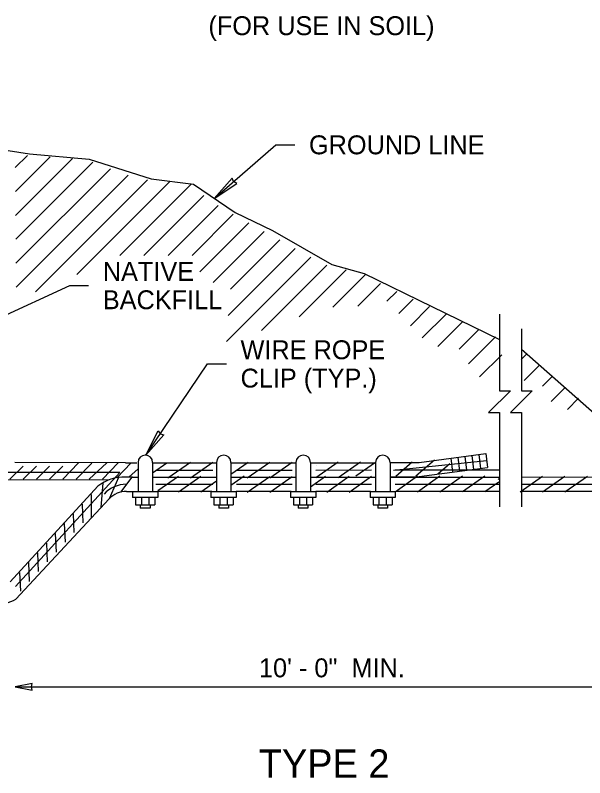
# Model space of a CAD drawing. Extents: x 99861 to 103151, y 100000 to 102076.
# Drawn here: x 100219 to 100701, y 100780 to 101426 of the extents above; entities that cross this region are included whole.
import ezdxf

# ---------------------------------------------------------------- set-up
doc = ezdxf.new("R2010")
doc.units = 0
for name, color, linetype in [('Level 1', 7, 'Continuous'), ('Level 10', 7, 'Continuous'), ('Level 15', 7, 'Continuous'), ('Level 18', 7, 'Continuous'), ('Level 20', 7, 'Continuous'), ('Level 28', 7, 'Continuous'), ('Level 3', 7, 'Continuous'), ('Level 4', 7, 'Continuous')]:
    doc.layers.add(name, color=color, linetype=linetype)

msp = doc.modelspace()

# ---------------------------------------------------------------- linework, layer by layer
at = {"layer": 'Level 1'}
for p, q in [((100616.94, 101054.52), (100618.49, 101042.62)), ((100312, 101046.45), (100218.25, 101047)), ((100312, 101046.45), (100321.65, 101046.45)), ((100473.91, 101043.94), (100473.91, 101043.94)), ((100317.76, 101034.45), (100312, 101034.45)), ((100317.76, 101034.45), (100322.9, 101034.45)), ((100297.67, 101032.04), (100153.96, 101032.42)), ((100312.8, 101022.45), (100317.94, 101022.45)), ((100219.24, 100931.28), (100298.16, 101016.07))]:
    msp.add_line(p, q, dxfattribs=at)
for points in [[(100628.45, 101172.45), (100628.45, 101107.66), (100637.74, 101107.66), (100619.16, 101089.08), (100628.45, 101089.08), (100628.45, 101029.73)], [(100647.03, 101159.99), (100647.03, 101107.66), (100656.32, 101107.66), (100637.74, 101089.08), (100647.03, 101089.08), (100647.03, 101009.35)], [(100535.91, 101046.94), (100560.43, 101046.86), (100616.94, 101054.52)], [(100335.57, 101046.46), (100388.82, 101046.48)], [(100401.24, 101046.48), (100455.96, 101046.5)], [(100468.57, 101046.51), (100523.17, 101046.53)], [(100535.91, 101034.78), (100560.45, 101035.03), (100618.49, 101042.62)], [(100334.89, 101034.45), (100388.92, 101034.48)], [(100401.23, 101034.48), (100456.26, 101034.5)], [(100468.57, 101034.51), (100523.6, 101034.53)], [(100535.91, 101034.53), (100628.45, 101034.56)], [(100647.37, 101034.57), (100762.09, 101034.61)], [(100288.57, 101026.8), (100214.43, 100945.81)], [(100628.45, 101029.63), (100628.45, 101009.35)], [(100339.33, 101022.46), (100385.06, 101022.47)], [(100405.62, 101022.48), (100452.16, 101022.5)], [(100472.96, 101022.51), (100519.36, 101022.53)], [(100540.96, 101022.53), (100628.45, 101022.56)], [(100647.37, 101022.57), (100772.65, 101022.61)]]:
    msp.add_lwpolyline(points, dxfattribs=at)
for centre, radius, start, end in [((100310.56, 100999.15), 35.32, 87.66549, 128.4992), ((100312.8, 101002.45), 20, 90, 137.05427), ((100200.93, 100963.29), 36.88, 270, 299.75989)]:
    msp.add_arc(centre, radius, start, end, dxfattribs=at)
at = {"layer": 'Level 10'}
for p, q in [((100218.67, 101296.56), (100228.94, 101306.83)), ((100218.67, 101296.56), (100228.94, 101306.83)), ((100218.82, 101276.34), (100248.08, 101305.61)), ((100218.97, 101256.13), (100267.22, 101304.38)), ((100219.12, 101235.91), (100284.3, 101301.09)), ((100219.12, 101235.91), (100284.3, 101301.09)), ((100219.27, 101215.7), (100299.23, 101295.66)), ((100219.42, 101195.48), (100314.17, 101290.23)), ((100235.65, 101191.35), (100330.45, 101286.15)), ((100235.65, 101191.35), (100330.45, 101286.15)), ((100270.73, 101206.06), (100349.12, 101284.45)), ((100307.24, 101222.21), (100367.79, 101282.76)), ((100327.6, 101222.21), (100378.25, 101272.86)), ((100327.6, 101222.21), (100378.25, 101272.86)), ((100347.97, 101222.21), (100390.33, 101264.57)), ((100368.33, 101222.21), (100403.21, 101257.09)), ((100374.92, 101208.43), (100416.33, 101249.84)), ((100374.92, 101208.43), (100416.33, 101249.84)), ((100386.11, 101199.26), (100429.44, 101242.59)), ((100400.96, 101193.74), (100442.56, 101235.34)), ((100398.81, 101171.23), (100455.67, 101228.09)), ((100398.81, 101171.23), (100455.67, 101228.09)), ((100397.39, 101149.44), (100468.79, 101220.84)), ((100427.04, 101158.73), (100482.32, 101214.01)), ((100459.02, 101170.35), (100498.61, 101209.94)), ((100487.48, 101178.44), (100514.73, 101205.68)), ((100508.56, 101179.15), (100527.74, 101198.33)), ((100533.19, 101183.42), (100541.53, 101191.76)), ((100533.19, 101183.42), (100541.53, 101191.76)), ((100543.19, 101173.06), (100555.39, 101185.25)), ((100553.2, 101162.7), (100569.4, 101178.9)), ((100563.2, 101152.34), (100583.41, 101172.54)), ((100563.2, 101152.34), (100583.41, 101172.54)), ((100576.2, 101144.97), (100597.42, 101166.19)), ((100594.4, 101142.81), (100611.43, 101159.84)), ((100602.37, 101130.41), (100625.2, 101153.25)), ((100602.37, 101130.41), (100625.2, 101153.25)), ((100611.75, 101119.43), (100630.41, 101138.09)), ((100646.77, 101134.08), (100651.91, 101139.22)), ((100649.42, 101116.37), (100662.35, 101129.3)), ((100649.42, 101116.37), (100662.35, 101129.3)), ((100664.89, 101111.47), (100672.79, 101119.38)), ((100672.34, 101098.56), (100683.84, 101110.06)), ((100686.03, 101091.88), (100695.41, 101101.27)), ((100686.03, 101091.88), (100695.41, 101101.27))]:
    msp.add_line(p, q, dxfattribs=at)
at = {"layer": 'Level 15'}
for p, q in [((100387.07, 101270.55), (100439.26, 101315.86)), ((100439.27, 101315.86), (100455.27, 101315.86)), ((100194.8, 101164.45), (100264.76, 101196.68)), ((100264.76, 101196.68), (100280.76, 101196.68)), ((100329.23, 101053.11), (100381.35, 101130.33)), ((100381.35, 101130.33), (100397.35, 101130.33)), ((100218.62, 100856.99), (100747.95, 100856.99))]:
    msp.add_line(p, q, dxfattribs=at)
for points in [[(100387.07, 101270.55), (100406.27, 101283.26), (100403.51, 101284.82), (100402.36, 101287.77)], [(100329.23, 101053.11), (100339.53, 101073.7), (100341.41, 101071.16), (100344.48, 101070.37)], [(100218.62, 100856.99), (100232.96, 100854.18), (100232.28, 100856.99), (100232.96, 100859.8)]]:
    msp.add_lwpolyline(points, close=True, dxfattribs=at)
at = {"layer": 'Level 28'}
for p, q in [((100322.59, 101046.98), (100322.58, 101022.67)), ((100334.9, 101046.97), (100334.89, 101022.67)), ((100388.93, 101046.97), (100388.91, 101022.66)), ((100401.24, 101046.96), (100401.22, 101022.65)), ((100456.27, 101046.96), (100456.25, 101022.65)), ((100468.57, 101046.95), (100468.56, 101022.64)), ((100523.6, 101046.94), (100523.59, 101022.64)), ((100535.91, 101046.94), (100535.9, 101022.63)), ((100317.94, 101022.45), (100339.28, 101022.41)), ((100384.28, 101022.44), (100405.62, 101022.39)), ((100451.62, 101022.42), (100472.96, 101022.38)), ((100518.96, 101022.41), (100540.3, 101022.37)), ((100339.28, 101017.31), (100317.94, 101017.32)), ((100325.51, 101017.21), (100325.51, 101010.97)), ((100331.59, 101017.31), (100331.58, 101010.96)), ((100336.71, 101017.31), (100336.71, 101010.96)), ((100405.62, 101017.3), (100384.28, 101017.31)), ((100391.85, 101017.19), (100391.85, 101010.96)), ((100397.92, 101017.3), (100397.92, 101010.95)), ((100403.05, 101017.3), (100403.05, 101010.95)), ((100472.95, 101017.29), (100451.62, 101017.3)), ((100459.19, 101017.18), (100459.18, 101010.94)), ((100465.26, 101017.29), (100465.26, 101010.94)), ((100470.39, 101017.29), (100470.39, 101010.94)), ((100540.29, 101017.27), (100518.95, 101017.29)), ((100526.53, 101017.17), (100526.52, 101010.93)), ((100532.6, 101017.28), (100532.6, 101010.93)), ((100537.73, 101017.27), (100537.72, 101010.92)), ((100324.5, 101010.97), (100324.5, 101008.16)), ((100332.71, 101008.16), (100324.5, 101008.16)), ((100331.41, 101008.16), (100326.34, 101008.16)), ((100332.71, 101010.96), (100332.71, 101008.16)), ((100390.84, 101010.96), (100390.84, 101008.15)), ((100399.05, 101008.15), (100390.84, 101008.15)), ((100397.75, 101008.15), (100392.68, 101008.15)), ((100399.05, 101010.95), (100399.05, 101008.15)), ((100458.18, 101010.94), (100458.18, 101008.14)), ((100466.38, 101008.13), (100458.18, 101008.14)), ((100465.08, 101008.13), (100460.02, 101008.14)), ((100466.38, 101010.94), (100466.38, 101008.13)), ((100525.52, 101010.93), (100525.51, 101008.13)), ((100533.72, 101008.12), (100525.51, 101008.13)), ((100532.42, 101008.12), (100527.36, 101008.13)), ((100533.72, 101010.93), (100533.72, 101008.12))]:
    msp.add_line(p, q, dxfattribs=at)
for points in [[(100317.94, 101022.45), (100317.94, 101017.32)], [(100339.28, 101022.41), (100339.28, 101017.31)], [(100384.28, 101022.44), (100384.28, 101017.31)], [(100405.62, 101022.39), (100405.62, 101017.3)], [(100451.62, 101022.42), (100451.62, 101017.3)], [(100472.96, 101022.38), (100472.95, 101017.29)], [(100518.96, 101022.41), (100518.95, 101017.29)], [(100540.3, 101022.37), (100540.29, 101017.27)], [(100320.51, 101017.32), (100320.5, 101010.97), (100336.71, 101010.96)], [(100386.84, 101017.31), (100386.84, 101010.96), (100403.05, 101010.95)], [(100454.18, 101017.3), (100454.18, 101010.95), (100470.39, 101010.94)], [(100521.52, 101017.28), (100521.52, 101010.93), (100537.72, 101010.92)]]:
    msp.add_lwpolyline(points, dxfattribs=at)
for centre in [(100328.74, 101046.98), (100395.08, 101046.97), (100462.42, 101046.95), (100529.76, 101046.94)]:
    msp.add_arc(centre, 6.15, 359.96715, 179.96715, dxfattribs=at)
at = {"layer": 'Level 3'}
for p, q in [((100181.21, 101316.19), (100230.65, 101308.17)), ((100230.65, 101308.17), (100281.27, 101303.59)), ((100281.27, 101303.59), (100333.64, 101286.99)), ((100333.64, 101286.99), (100369.39, 101282.61)), ((100369.39, 101282.61), (100404.75, 101258.49)), ((100404.75, 101258.49), (100436.44, 101243.42)), ((100647.03, 101142.97), (100753.72, 101048.58))]:
    msp.add_line(p, q, dxfattribs=at)
msp.add_lwpolyline([(100436.44, 101243.42), (100486.67, 101214.59), (100513.95, 101206.9), (100628.45, 101150.94)], dxfattribs=at)
at = {"layer": 'Level 4'}
for p, q in [((100605.06, 101052.83), (100606.59, 101041.07)), ((100610.99, 101053.74), (100612.54, 101041.85)), ((100258.9, 101032.69), (100272.14, 101046.68)), ((100270.1, 101032.69), (100283.6, 101046.2)), ((100281.3, 101032.69), (100296.1, 101046.54)), ((100292.5, 101032.69), (100305.7, 101046.48)), ((100304.61, 101033.97), (100316.82, 101046.45)), ((100334.89, 101038), (100346.95, 101046.46)), ((100347.9, 101033.81), (100366.89, 101047.12)), ((100366.9, 101033.82), (100385.89, 101047.13)), ((100401.23, 101036.9), (100415.85, 101047.14)), ((100415.01, 101033.83), (100434, 101047.14)), ((100434.01, 101033.84), (100453, 101047.15)), ((100491.94, 101047.17), (100472.94, 101033.86)), ((100491.94, 101047.17), (100472.94, 101033.86)), ((100510.93, 101047.17), (100491.94, 101033.86)), ((100510.93, 101047.17), (100491.94, 101033.86)), ((100523.6, 101046.94), (100507.06, 101035.35)), ((100554.75, 101047.13), (100540.78, 101035.04)), ((100573.52, 101048.96), (100557.78, 101035.34)), ((100586.42, 101045.72), (100576.36, 101037.01)), ((100587.21, 101050.49), (100588.75, 101038.73)), ((100593.16, 101051.27), (100594.7, 101039.51)), ((100599.11, 101052.05), (100600.65, 101040.29)), ((100214.1, 101032.69), (100225.3, 101043.89)), ((100225.3, 101032.69), (100236.5, 101043.89)), ((100236.5, 101032.69), (100247.7, 101043.89)), ((100247.7, 101032.69), (100258.9, 101043.89)), ((100314.88, 101034.45), (100322.59, 101041.42)), ((100306.05, 101034.19), (100298.16, 101016.07)), ((100317.38, 101034.45), (100307.85, 101021.78)), ((100356.77, 101035.11), (100339.33, 101022.89)), ((100375.77, 101035.12), (100356.78, 101021.81)), ((100401.23, 101027.64), (100412.39, 101035.46)), ((100415.01, 101021.83), (100434.01, 101035.14)), ((100415.01, 101021.83), (100434.01, 101035.14)), ((100434.01, 101021.84), (100453.01, 101035.15)), ((100434.01, 101021.84), (100453.01, 101035.15)), ((100468.56, 101026.19), (100481.38, 101035.17)), ((100482.25, 101021.86), (100501.24, 101035.17)), ((100482.25, 101021.86), (100501.24, 101035.17)), ((100501.25, 101021.87), (100520.24, 101035.18)), ((100501.25, 101021.87), (100520.24, 101035.18)), ((100559.14, 101035.19), (100540.14, 101021.88)), ((100578.14, 101035.2), (100559.14, 101021.89)), ((100597.14, 101035.2), (100578.14, 101021.89)), ((100616.14, 101035.21), (100597.14, 101021.9)), ((100628.23, 101033.41), (100627.39, 101032.56)), ((100645.98, 101021.91), (100664.97, 101035.22)), ((100664.98, 101021.92), (100683.97, 101035.23)), ((100683.98, 101021.93), (100702.97, 101035.24)), ((100292.67, 101029.61), (100291.03, 101008.79)), ((100388.92, 101031.03), (100375.78, 101021.82)), ((100628.03, 101030.23), (100616.14, 101021.9)), ((100282.79, 101019.89), (100283, 100999.79)), ((100275.22, 101011.63), (100275.92, 100995.81)), ((100267.66, 101003.37), (100268.36, 100987.55)), ((100260.1, 100995.11), (100260.8, 100979.28)), ((100252.54, 100986.85), (100253.23, 100971.02)), ((100244.97, 100978.59), (100245.67, 100962.76)), ((100237.41, 100970.33), (100238.11, 100954.5)), ((100229.85, 100962.07), (100230.54, 100946.24)), ((100222.28, 100953.8), (100222.98, 100937.98))]:
    msp.add_line(p, q, dxfattribs=at)
for points in [[(100538.69, 101040.43), (100617.88, 101048.59)], [(100337.77, 101040.46), (100385.89, 101040.47)], [(100405.87, 101040.48), (100453, 101040.5)], [(100472.94, 101040.51), (100520.24, 101040.53)], [(100540.14, 101040.53), (100628.45, 101040.56)], [(100218.85, 100941.76), (100307.22, 101038.29), (100203.85, 101038.29)], [(100337.77, 101028.46), (100385.9, 101028.47)], [(100405.87, 101028.48), (100453.01, 101028.5)], [(100472.94, 101028.51), (100520.24, 101028.53)], [(100540.14, 101028.53), (100628.45, 101028.56)], [(100647.37, 101028.57), (100772.64, 101028.61)]]:
    msp.add_lwpolyline(points, dxfattribs=at)
msp.add_arc((100312.8, 101002.45), 26, 90, 137.05427, dxfattribs=at)

# ---------------------------------------------------------------- texts
at = {"layer": 'Level 18'}
for s, height, p in [('(FOR USE IN SOIL)', 16, (100382.16, 101408.74)), ('TYPE 2', 24, (100424.78, 100779.93))]:
    msp.add_text(s, height=height, dxfattribs=at).set_placement(p)
at = {"layer": 'Level 20'}
for s, p in [('GROUND LINE', (100467.27, 101307.86)), ('NATIVE', (100292.76, 101200.68)), ('BACKFILL', (100292.76, 101176.68)), ('WIRE ROPE', (100409.35, 101134.33)), ('CLIP (TYP.)', (100409.35, 101110.33)), ('10\' - 0"  MIN.', (100424.95, 100864.99))]:
    msp.add_text(s, height=16, dxfattribs=at).set_placement(p)

doc.saveas('drawing.dxf')
